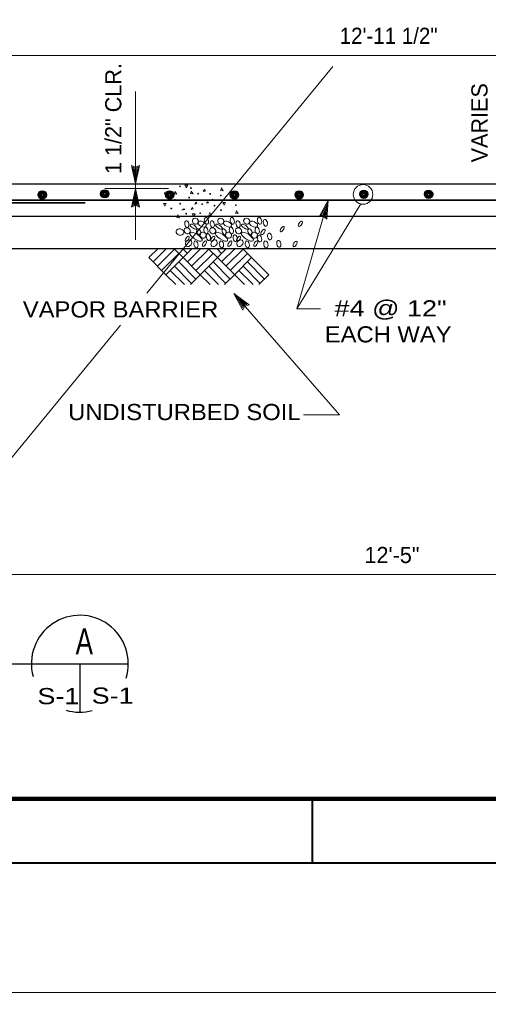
# Model space of a CAD drawing. Extents: x -24.3 to 17.7, y -17.6 to 12.4.
# Drawn here: x -9.61 to -5.98, y -17.61 to -10.08 of the extents above; entities that cross this region are included whole.
import ezdxf
from ezdxf.enums import TextEntityAlignment as Align

# ---------------------------------------------------------------- set-up
doc = ezdxf.new("R2010")
doc.units = 0
doc.header["$LTSCALE"] = 0.05
doc.layers.add('1', color=7, linetype='Continuous', lineweight=13)
doc.layers.add('2', color=7, linetype='Continuous', lineweight=13)

msp = doc.modelspace()

# ---------------------------------------------------------------- linework, layer by layer
at = {"layer": '1'}
for p, q in [((-8.62169, -12.1996), (-7.18169, -10.4466)), ((-8.70969, -11.3546), (-8.70969, -10.6396)), ((-8.70969, -11.3546), (-8.74069, -11.2106)), ((-8.70969, -11.3546), (-8.67869, -11.2106)), ((-8.70969, -11.3176), (-8.72969, -11.2236)), ((-8.72969, -11.2236), (-8.70969, -11.2326)), ((-8.70969, -11.2816), (-8.71969, -11.2366)), ((-8.71969, -11.2366), (-8.70969, -11.2406)), ((-8.70969, -11.3176), (-8.68969, -11.2236)), ((-8.70969, -11.2326), (-8.68969, -11.2236)), ((-8.70969, -11.2816), (-8.70069, -11.2366)), ((-8.70969, -11.2406), (-8.70069, -11.2366)), ((-8.94669, -11.3886), (-8.45269, -11.3886)), ((-8.70969, -11.3896), (-8.74069, -11.5336)), ((-8.70969, -11.4266), (-8.72969, -11.5206)), ((-8.70969, -11.3896), (-8.67869, -11.5336)), ((-8.70969, -11.4266), (-8.68969, -11.5206)), ((-8.70969, -11.5116), (-8.72969, -11.5206)), ((-8.70969, -11.4626), (-8.71869, -11.5076)), ((-8.70969, -11.5036), (-8.71869, -11.5076)), ((-8.70969, -11.4626), (-8.69969, -11.5076)), ((-8.69969, -11.5076), (-8.70969, -11.5036)), ((-8.68969, -11.5206), (-8.70969, -11.5116)), ((-7.46069, -12.3206), (-6.96669, -11.5086)), ((-7.21969, -11.4796), (-7.28869, -11.6096)), ((-7.22969, -11.5156), (-7.27469, -11.5996)), ((-7.22969, -11.5156), (-7.23669, -11.6106)), ((-7.23969, -11.5496), (-7.26069, -11.5906)), ((-7.25069, -11.5896), (-7.26069, -11.5906)), ((-7.24269, -11.5956), (-7.25069, -11.5896)), ((-7.23969, -11.5496), (-7.24269, -11.5956)), ((-7.25369, -11.5966), (-7.27469, -11.5996)), ((-7.23669, -11.6106), (-7.25369, -11.5966)), ((-8.60569, -11.9246), (-8.53469, -11.8536)), ((-8.57269, -11.9576), (-8.46869, -11.8536)), ((-8.53969, -11.9906), (-8.40669, -11.8586)), ((-8.50669, -12.0246), (-8.37369, -11.8916)), ((-8.34069, -11.9246), (-8.41169, -11.8536)), ((-8.30769, -11.8916), (-8.34569, -11.8536)), ((-8.34069, -11.9246), (-8.26969, -11.8536)), ((-8.34069, -11.9246), (-8.26969, -11.8536)), ((-8.30769, -11.9576), (-8.20369, -11.8536)), ((-8.27469, -11.8586), (-8.27969, -11.8536)), ((-8.27469, -11.9906), (-8.14169, -11.8586)), ((-8.24169, -12.0246), (-8.10869, -11.8916)), ((-8.07569, -11.9246), (-8.14669, -11.8536)), ((-8.04269, -11.8916), (-8.08069, -11.8536)), ((-8.07569, -11.9246), (-8.00469, -11.8536)), ((-8.04269, -11.9576), (-7.93769, -11.8536)), ((-8.00969, -11.8586), (-8.01369, -11.8536)), ((-8.00969, -11.9906), (-7.87669, -11.8586)), ((-7.97569, -12.0246), (-7.84369, -11.8916)), ((-7.81069, -11.9246), (-7.88169, -11.8536)), ((-8.47369, -12.0576), (-8.34069, -11.9246)), ((-8.24169, -12.0906), (-8.37369, -11.9576)), ((-8.20769, -12.0576), (-8.34069, -11.9246)), ((-8.20769, -12.0576), (-8.07569, -11.9246)), ((-7.97569, -12.0906), (-8.10869, -11.9576)), ((-7.94269, -12.0576), (-7.81069, -11.9246)), ((-7.71069, -12.0906), (-7.84369, -11.9576)), ((-7.67769, -12.0576), (-7.81069, -11.9246)), ((-8.33069, -12.1336), (-8.44069, -12.0246)), ((-8.27469, -12.1236), (-8.40669, -11.9906)), ((-8.06569, -12.1336), (-8.17469, -12.0246)), ((-8.00969, -12.1236), (-8.14169, -11.9906)), ((-7.79969, -12.1336), (-7.90969, -12.0246)), ((-7.74369, -12.1236), (-7.87669, -11.9906)), ((-8.28469, -12.1336), (-8.20769, -12.0576)), ((-8.13169, -12.1336), (-8.20769, -12.0576)), ((-8.01969, -12.1336), (-7.94269, -12.0576)), ((-7.75469, -12.1336), (-7.67769, -12.0576)), ((-7.94869, -12.2016), (-7.87769, -12.3306)), ((-7.92469, -12.2296), (-7.84769, -12.2876)), ((-7.92469, -12.2296), (-7.87769, -12.3136)), ((-7.90069, -12.2566), (-7.87769, -12.2966)), ((-7.90069, -12.2566), (-7.86369, -12.2836)), ((-7.87369, -12.2876), (-7.87769, -12.2966)), ((-7.86869, -12.2936), (-7.87769, -12.3136)), ((-7.86369, -12.2836), (-7.87369, -12.2876)), ((-7.84769, -12.2876), (-7.86869, -12.2936)), ((-7.46069, -12.3206), (-7.27769, -12.3206)), ((-9.90869, -13.7666), (-8.82569, -12.4476)), ((17.65731, -17.6106), (-24.34269, -17.6106))]:
    msp.add_line(p, q, dxfattribs=at)
at = {"layer": '1', "lineweight": 25}
for p, q in [((-16.07569, -11.3546), (-3.74269, -11.3546)), ((-16.07569, -11.6046), (-3.74269, -11.6046)), ((-16.07569, -11.8546), (-3.74269, -11.8546)), ((-11.47369, -15.0666), (-8.76469, -15.0666)), ((-9.13969, -15.0666), (-9.13969, -15.4416))]:
    msp.add_line(p, q, dxfattribs=at)
at = {"layer": '1', "lineweight": 35}
for p, q in [((-10.68781, -11.50146), (-9.09967, -11.50146)), ((-9.84169, -11.4796), (-3.67137, -11.4796))]:
    msp.add_line(p, q, dxfattribs=at)
at = {"layer": '1', "lineweight": 40}
msp.add_line((-7.34269, -16.1106), (-7.34269, -16.6106), dxfattribs=at)
msp.add_lwpolyline([(-23.34269, -16.6106), (-23.34269, 11.3894), (16.65731, 11.3894), (16.65731, -16.6106)], close=True, dxfattribs=at)
at = {"layer": '1', "lineweight": 90}
msp.add_lwpolyline([(-21.84269, 10.8894), (16.15731, 10.8894), (16.15731, -16.1106), (-21.84269, -16.1106)], close=True, dxfattribs=at)
at = {"layer": '1'}
for points in [[(-16.38769, -10.3596), (-9.90869, -10.3596), (-3.42969, -10.3596), (-3.57369, -10.3906)], [(-8.74069, -11.2106), (-8.70969, -11.2246), (-8.67869, -11.2106)], [(-8.70969, -11.3546), (-8.70969, -11.3896), (-8.70969, -11.7856)], [(-7.46069, -12.3206), (-7.21969, -11.4796), (-7.22969, -11.6266)], [(-8.67869, -11.5336), (-8.70969, -11.5196), (-8.74069, -11.5336)], [(-7.22969, -11.6266), (-7.25569, -11.6046), (-7.28869, -11.6096)], [(-7.86669, -12.1336), (-8.07569, -11.9246), (-8.00469, -11.8536)], [(-8.39669, -12.1336), (-8.47369, -12.0576), (-8.60569, -11.9246)], [(-7.40969, -13.1406), (-7.13169, -13.1406), (-7.94869, -12.2016), (-7.83069, -12.2896)], [(-7.83069, -12.2896), (-7.86369, -12.2996), (-7.87769, -12.3306)], [(-16.07669, -14.3756), (-9.90869, -14.3756), (-3.74269, -14.3756)]]:
    msp.add_lwpolyline(points, dxfattribs=at)
msp.add_circle((-6.94869, -11.4356), 0.07566, dxfattribs=at)
at = {"layer": '1', "lineweight": 25}
for centre, radius in [((-9.4307, -11.43913), 0.0319), ((-9.4307, -11.43913), 0.02658), ((-9.4307, -11.43913), 0.02215), ((-9.4307, -11.43913), 0.01846), ((-9.4307, -11.43913), 0.01538), ((-9.4307, -11.43913), 0.01282), ((-9.4307, -11.43913), 0.01068), ((-9.4307, -11.43913), 0.0089), ((-8.94672, -11.43113), 0.0319), ((-8.94672, -11.43113), 0.02658), ((-8.94672, -11.43113), 0.02215), ((-8.94672, -11.43113), 0.01846), ((-8.94672, -11.43113), 0.01538), ((-8.94672, -11.43113), 0.01282), ((-8.94672, -11.43113), 0.01068), ((-8.94672, -11.43113), 0.0089), ((-8.44473, -11.43913), 0.0319), ((-8.44473, -11.43913), 0.02658), ((-8.44473, -11.43913), 0.02215), ((-8.44473, -11.43913), 0.01846), ((-8.44473, -11.43913), 0.01538), ((-8.44473, -11.43913), 0.01282), ((-8.44473, -11.43913), 0.01068), ((-8.44473, -11.43913), 0.0089), ((-7.94375, -11.43913), 0.0319), ((-7.94375, -11.43913), 0.02658), ((-7.94375, -11.43913), 0.02215), ((-7.94375, -11.43913), 0.01846), ((-7.94375, -11.43913), 0.01538), ((-7.94375, -11.43913), 0.01282), ((-7.94375, -11.43913), 0.01068), ((-7.94375, -11.43913), 0.0089), ((-7.44277, -11.43913), 0.0319), ((-7.44277, -11.43913), 0.02658), ((-7.44277, -11.43913), 0.02215), ((-7.44277, -11.43913), 0.01846), ((-7.44277, -11.43913), 0.01538), ((-7.44277, -11.43913), 0.01282), ((-7.44277, -11.43913), 0.01068), ((-7.44277, -11.43913), 0.0089), ((-6.94278, -11.43413), 0.0319), ((-6.94278, -11.43413), 0.02658), ((-6.94278, -11.43413), 0.02215), ((-6.94278, -11.43413), 0.01846), ((-6.94278, -11.43413), 0.01538), ((-6.94278, -11.43413), 0.01282), ((-6.94278, -11.43413), 0.01068), ((-6.94278, -11.43413), 0.0089), ((-6.4418, -11.43413), 0.0319), ((-6.4418, -11.43413), 0.02658), ((-6.4418, -11.43413), 0.02215), ((-6.4418, -11.43413), 0.01846), ((-6.4418, -11.43413), 0.01538), ((-6.4418, -11.43413), 0.01282), ((-6.4418, -11.43413), 0.01068), ((-6.4418, -11.43413), 0.0089)]:
    msp.add_circle(centre, radius, dxfattribs=at)
for start, end in [(342.70891, 195.26862), (253.4742, 284.92162)]:
    msp.add_arc((-9.13969, -15.0666), 0.375, start, end, dxfattribs=at)
at = {"layer": '1'}
for centre, major_axis, ratio in [((-8.31219, -11.6656), (-0.0055, 0.026), 0.599528), ((-8.25969, -11.6856), (-0.026, 0.017), 0.365968), ((-8.24569, -11.6431), (-0.02021, 0.0142), 0.915279), ((-8.19419, -11.6646), (-0.0315, 0.015), 0.562188), ((-8.16019, -11.6396), (-0.0055, 0.026), 0.599528), ((-8.11519, -11.6656), (-0.0055, 0.026), 0.599528), ((-8.06269, -11.6856), (-0.026, 0.017), 0.365968), ((-8.04869, -11.6431), (-0.02021, 0.0142), 0.915279), ((-7.99719, -11.6646), (-0.0315, 0.015), 0.562188), ((-7.96019, -11.6396), (-0.0055, 0.026), 0.599528), ((-7.91519, -11.6656), (-0.0055, 0.026), 0.599528), ((-7.86269, -11.6856), (-0.026, 0.017), 0.365968), ((-7.84869, -11.6431), (-0.02021, 0.0142), 0.915279), ((-7.79719, -11.6646), (-0.0315, 0.015), 0.562188), ((-7.74919, -11.6396), (-0.0055, 0.026), 0.599528), ((-7.70419, -11.6546), (-0.0055, 0.026), 0.599528), ((-7.43369, -11.6631), (0.013, 0.0205), 0.445558), ((-8.36519, -11.7266), (-0.03038, 0.00696), 0.790099), ((-8.30869, -11.7171), (-0.02021, 0.0142), 0.915279), ((-8.24069, -11.7631), (-0.04615, 0.03077), 0.357541), ((-8.21969, -11.7251), (-0.009, 0.0225), 0.615421), ((-8.18669, -11.7501), (-0.02021, 0.0142), 0.915279), ((-8.16419, -11.7146), (-0.0055, 0.026), 0.599528), ((-8.14519, -11.7656), (-0.0055, 0.026), 0.599528), ((-8.11169, -11.7171), (-0.02021, 0.0142), 0.915279), ((-8.04369, -11.7631), (-0.04615, 0.03077), 0.357541), ((-8.02269, -11.7251), (-0.009, 0.0225), 0.615421), ((-7.98969, -11.7501), (-0.02021, 0.0142), 0.915279), ((-7.96719, -11.7146), (-0.0055, 0.026), 0.599528), ((-7.91169, -11.7171), (-0.02021, 0.0142), 0.915279), ((-7.84369, -11.7631), (-0.04615, 0.03077), 0.357541), ((-7.82269, -11.7251), (-0.009, 0.0225), 0.615421), ((-7.78969, -11.7501), (-0.02021, 0.0142), 0.915279), ((-7.76719, -11.7146), (-0.0055, 0.026), 0.599528), ((-7.72269, -11.7261), (0.013, 0.0205), 0.445558), ((-7.67119, -11.7616), (-0.0055, 0.026), 0.599528), ((-7.57469, -11.7041), (0.013, 0.0205), 0.445558), ((-8.30869, -11.7791), (0.013, 0.0205), 0.445558), ((-8.29819, -11.8131), (0.0165, 0.0225), 0.822116), ((-8.24119, -11.8216), (-0.0055, 0.026), 0.599528), ((-8.17569, -11.8161), (0.013, 0.0205), 0.445558), ((-8.11169, -11.7791), (0.013, 0.0205), 0.445558), ((-8.10119, -11.8131), (0.0165, 0.0225), 0.822116), ((-8.04419, -11.8216), (-0.0055, 0.026), 0.599528), ((-7.97869, -11.8161), (0.013, 0.0205), 0.445558), ((-7.93819, -11.7736), (-0.0055, 0.026), 0.599528), ((-7.91169, -11.7791), (0.013, 0.0205), 0.445558), ((-7.90119, -11.8131), (0.0165, 0.0225), 0.822116), ((-7.84419, -11.8216), (-0.0055, 0.026), 0.599528), ((-7.77869, -11.8161), (0.013, 0.0205), 0.445558), ((-7.74919, -11.7766), (-0.0055, 0.026), 0.599528), ((-7.70019, -11.8216), (-0.0055, 0.026), 0.599528), ((-7.60019, -11.8176), (-0.0055, 0.026), 0.599528), ((-7.47469, -11.8191), (0.013, 0.0205), 0.445558)]:
    msp.add_ellipse(centre, major_axis=major_axis, ratio=ratio, dxfattribs=at)
at = {"layer": '2'}
msp.add_line((-8.18469, -11.4066), (-8.17369, -11.3966), dxfattribs=at)
for points in [[(-8.31669, -11.3816), (-8.32669, -11.3646), (-8.30469, -11.3646), (-8.31669, -11.3846)], [(-8.39869, -11.4116), (-8.40869, -11.4316), (-8.38869, -11.4336), (-8.40369, -11.4116)], [(-8.27469, -11.4096), (-8.28469, -11.4296), (-8.26369, -11.4316), (-8.27969, -11.4096)], [(-8.17369, -11.3946), (-8.16969, -11.4096), (-8.18469, -11.4096)], [(-8.04069, -11.3846), (-8.05069, -11.4046), (-8.02969, -11.4066), (-8.04569, -11.3846)], [(-8.48269, -11.5226), (-8.49269, -11.5056), (-8.47069, -11.5056), (-8.48269, -11.5266)], [(-8.15969, -11.5006), (-8.15269, -11.4926), (-8.14469, -11.5006), (-8.15769, -11.5026)], [(-8.11969, -11.4756), (-8.10969, -11.4716), (-8.10469, -11.4826), (-8.11969, -11.4776)], [(-8.02369, -11.5146), (-8.03369, -11.4976), (-8.01169, -11.4976), (-8.02369, -11.5176)], [(-8.37869, -11.5936), (-8.38869, -11.6136), (-8.36869, -11.6156), (-8.38369, -11.5936)], [(-8.34469, -11.5526), (-8.33469, -11.5466), (-8.32669, -11.5526), (-8.34969, -11.5566)], [(-8.26069, -11.6036), (-8.27069, -11.5866), (-8.24869, -11.5866), (-8.26069, -11.6066)], [(-8.13269, -11.5766), (-8.14269, -11.5966), (-8.12269, -11.5986), (-8.13769, -11.5766)], [(-7.92569, -11.5616), (-7.93569, -11.5816), (-7.91569, -11.5836), (-7.93069, -11.5616)]]:
    msp.add_lwpolyline(points, dxfattribs=at)
for points in [[(-8.24969, -11.5096), (-8.23969, -11.4926), (-8.23369, -11.5046)], [(-8.27969, -11.5526), (-8.26969, -11.5356), (-8.26369, -11.5476)]]:
    msp.add_lwpolyline(points, close=True, dxfattribs=at)
for centre in [(-8.48148, -11.42639), (-8.36498, -11.37289), (-8.27948, -11.38639), (-8.22399, -11.42989), (-8.13149, -11.43189), (-8.04899, -11.44339), (-8.40198, -11.47689), (-8.36348, -11.50739), (-8.29448, -11.46039), (-8.19349, -11.51089), (-7.93249, -11.51889), (-8.43248, -11.54439), (-8.31648, -11.58489), (-8.20849, -11.57989), (-8.09749, -11.52239), (-8.04699, -11.55789)]:
    msp.add_circle(centre, 0.00325, dxfattribs=at)

# ---------------------------------------------------------------- texts
at = {"layer": '1'}
for s, height, width, p in [('12\'-11 1/2"', 0.125, 0.95, (-6.75069, -10.2706)), ('#4 @ 12"', 0.125, 1.25, (-6.73569, -12.3796)), ('EACH WAY', 0.125, 1.1, (-6.75419, -12.5806)), ('UNDISTURBED SOIL', 0.125, 1.1, (-8.33119, -13.1816)), ('A', 0.2, 0.75, (-9.10519, -14.9926)), ('S-1', 0.125, 1.25, (-9.30569, -15.3796)), ('S-1', 0.125, 1.25, (-8.88569, -15.3756))]:
    msp.add_text(s, height=height, dxfattribs=dict(at, width=width)).set_placement(p, align=Align.CENTER)
for s, p in [('1 1/2" CLR.', (-8.81869, -11.2776)), ('VARIES', (-5.98569, -11.1876))]:
    msp.add_text(s, height=0.125, rotation=90, dxfattribs=at).set_placement(p)
at = {"layer": '1', "width": 1.1}
msp.add_text('VAPOR BARRIER', height=0.125, dxfattribs=at).set_placement((-9.58069, -12.3876))
at = {"layer": '1'}
msp.add_text('12\'-5"', height=0.125, dxfattribs=at).set_placement((-6.72469, -14.2876), align=Align.CENTER)

doc.saveas('drawing.dxf')
